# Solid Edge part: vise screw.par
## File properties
Title: Vise Screw
Author: Abhinav Rai
Template: Normal.par
Last saved by: CADCIM
Revision: 6
Application: Solid Edge
Density: 0.0000078 kg/mm^3
Accuracy: 0.01
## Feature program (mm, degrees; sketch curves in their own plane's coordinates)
sketch for "unnamed RevolvedProtrusion 1" plane through (0, 0, 0) normal (0, -1, 0) x-axis (1, 0, 0)
  line (9.525, 77.2518) -> (9.525, 56.627)
  line (9.525, 56.627) -> (6.35, 56.627)
  line (6.35, 56.627) -> (6.35, 50.277)
  line (6.35, 50.277) -> (7.9375, 50.277)
  line (7.9375, 50.277) -> (7.9375, -49.7228)
  line (7.9375, -49.7228) -> (6.35, -49.7228)
  line (6.35, -49.7228) -> (6.35, -72.5828)
  line (6.35, -72.5828) -> (4.7625, -72.5828)
  line (4.7625, -72.5828) -> (4.7625, -75.1482)
  line (4.7625, -75.1482) -> (6.35, -75.1482)
  line (6.35, -75.1482) -> (6.35, -81.4982)
  line (6.35, -81.4982) -> (0, -81.4982)
  line (0, -81.4982) -> (0, 77.2518)
  line (0, 77.2518) -> (9.525, 77.2518)
revolve "unnamed RevolvedProtrusion 1" add finite 360 deg
sketch for "unnamed Hole 1" plane through (0, 0, 0) normal (0, -1, 0) x-axis (1, 0, 0)
  hole centre (0, 66.9394) bore radius 4.3688
hole "unnamed Hole 1" through
sketch for "unnamed Hole 2" plane through (0, 0, 0) normal (0, -1, 0) x-axis (1, 0, 0)
  hole centre (0, 66.9394) bore radius 4.3688
hole "unnamed Hole 2" through
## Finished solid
Body 1: solid body, 14 faces, 14 edges, 0 vertices.
  Faces by surface: cylinder 7, plane 7
  Edges by curve: circle 12, intersection 2
Bounding box of the edges (mm): 19.050 x 19.050 x 158.750, from (-9.525, -9.525, -81.4982) to (9.525, 9.525, 77.2518).
Cylindrical faces by radius (mm): R4.3688 x1, R4.7625 x1, R6.35 x3, R7.9375 x1, R9.525 x1
Planar faces by outward normal: +z 3, -z 4
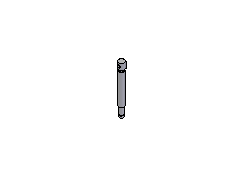
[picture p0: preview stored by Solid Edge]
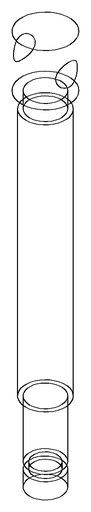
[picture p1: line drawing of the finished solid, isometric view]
